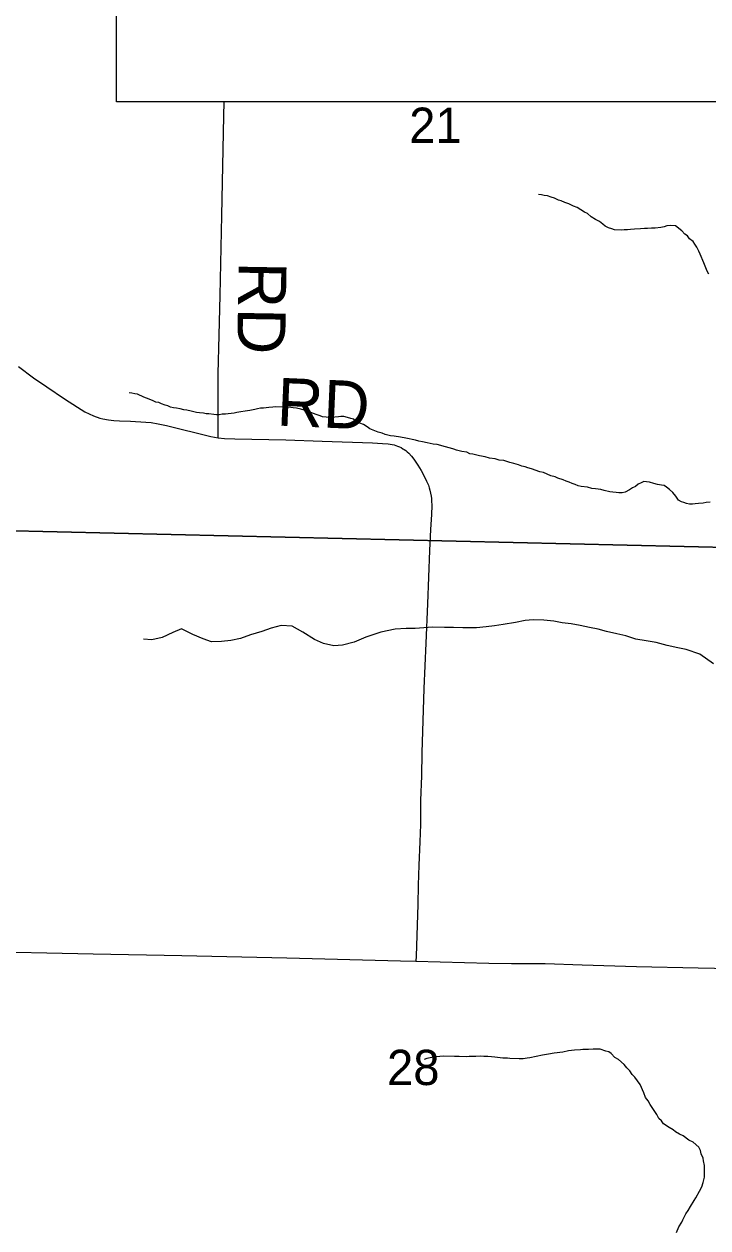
# Model space of a CAD drawing. Extents: x 0 to 34, y 0 to 22.
# Drawn here: x 25.055 to 25.461, y 15.938 to 16.653 of the extents above; entities that cross this region are included whole.
import ezdxf

# ---------------------------------------------------------------- set-up
doc = ezdxf.new("R2010")
doc.units = 0
for name, color, linetype in [('GM_X_Minor_River', 7, 'Continuous'), ('GM_X_Section', 7, 'Continuous'), ('GM_X_Section_Text', 7, 'Continuous'), ('GM_X_Township_Road', 7, 'Continuous'), ('GM_X_Township_Road_Text', 7, 'Continuous'), ('SH_Text', 7, 'Continuous')]:
    doc.layers.add(name, color=color, linetype=linetype)

msp = doc.modelspace()

# ---------------------------------------------------------------- linework, layer by layer
at = {"layer": 'GM_X_Minor_River'}
for points in [[(25.46134, 16.50449), (25.46045, 16.50623), (25.45956, 16.50816), (25.45853, 16.51124), (25.45624, 16.51627), (25.45554, 16.5182), (25.4543, 16.52053), (25.45303, 16.52228), (25.45213, 16.52384), (25.44991, 16.52544), (25.44883, 16.52719), (25.44715, 16.5282), (25.44532, 16.53017), (25.44162, 16.53315), (25.43878, 16.53344), (25.43649, 16.53314), (25.43495, 16.53262), (25.43303, 16.53212), (25.4296, 16.53186), (25.4275, 16.53174), (25.42503, 16.53163), (25.42331, 16.5315), (25.42084, 16.5314), (25.41741, 16.53114), (25.41493, 16.53104), (25.41321, 16.5309), (25.41112, 16.53079), (25.40959, 16.53065), (25.40542, 16.5308), (25.40392, 16.53142), (25.40185, 16.53206), (25.39998, 16.53308), (25.3985, 16.53408), (25.39646, 16.53568), (25.39422, 16.5369), (25.39162, 16.53851), (25.38941, 16.54049), (25.38772, 16.54131), (25.38326, 16.54413), (25.38119, 16.54477), (25.37839, 16.5462), (25.37595, 16.54705), (25.37389, 16.54807), (25.3722, 16.54851), (25.36995, 16.54954), (25.36788, 16.55018), (25.36563, 16.55102), (25.36374, 16.55128), (25.36223, 16.55152), (25.36033, 16.55178)], [(25.1971, 16.42503), (25.19539, 16.4249), (25.19367, 16.42458), (25.19213, 16.42406), (25.18907, 16.4236), (25.18639, 16.42312), (25.18372, 16.42283), (25.18142, 16.42234), (25.1797, 16.42202), (25.17626, 16.42157), (25.17473, 16.42143), (25.17264, 16.42132), (25.17091, 16.421), (25.1692, 16.42106), (25.16769, 16.42111), (25.16466, 16.4216), (25.16314, 16.42165), (25.16163, 16.42189), (25.15917, 16.42217), (25.15746, 16.42242), (25.15426, 16.4231), (25.15162, 16.42376), (25.14992, 16.42401), (25.14765, 16.42447), (25.14558, 16.42493), (25.14387, 16.42518), (25.14199, 16.42562), (25.14049, 16.42625), (25.13879, 16.42669), (25.13673, 16.42752), (25.13505, 16.42834), (25.13335, 16.42859), (25.13128, 16.42942), (25.12772, 16.43088), (25.12622, 16.4315), (25.12248, 16.43316), (25.12078, 16.43341), (25.11908, 16.43385), (25.11738, 16.4341)], [(25.43634, 16.37803), (25.43485, 16.37904), (25.43334, 16.37928), (25.43107, 16.37955), (25.42881, 16.3802), (25.42618, 16.38105), (25.42448, 16.3813), (25.42277, 16.38136), (25.42122, 16.38065), (25.41948, 16.37976), (25.41791, 16.37849), (25.41617, 16.3776), (25.41442, 16.37652), (25.41171, 16.37509), (25.40999, 16.37477), (25.40808, 16.37464), (25.40638, 16.37489), (25.40449, 16.37515), (25.40278, 16.37521), (25.39939, 16.37609), (25.39732, 16.37673), (25.3958, 16.37679), (25.3941, 16.37704), (25.39201, 16.3773), (25.38938, 16.37796), (25.38559, 16.37848), (25.3839, 16.37892), (25.38221, 16.37954), (25.38033, 16.38018), (25.37846, 16.38101), (25.37677, 16.38164), (25.3749, 16.38247), (25.37188, 16.38333), (25.3702, 16.38415), (25.36775, 16.38481), (25.36326, 16.38668), (25.36118, 16.38713), (25.35611, 16.38902), (25.35404, 16.38947), (25.35254, 16.3901), (25.35046, 16.39055), (25.34859, 16.39138), (25.34576, 16.39205), (25.34331, 16.3927), (25.33974, 16.39378), (25.33709, 16.39406), (25.33465, 16.39491), (25.33123, 16.39522), (25.32879, 16.39607), (25.32539, 16.39657), (25.32143, 16.39766), (25.31954, 16.39791), (25.31786, 16.39873), (25.31483, 16.39922), (25.31163, 16.40009), (25.31013, 16.40052), (25.30806, 16.40117), (25.30429, 16.40225), (25.30241, 16.4027), (25.30015, 16.40335), (25.29788, 16.40362), (25.29599, 16.40406), (25.29429, 16.40431), (25.29146, 16.40498), (25.28938, 16.40525), (25.28731, 16.40589), (25.28165, 16.40704), (25.27844, 16.40772), (25.27466, 16.40824), (25.27257, 16.4085), (25.26937, 16.40937), (25.26768, 16.41), (25.26523, 16.41066), (25.26036, 16.41273), (25.2587, 16.41393), (25.25646, 16.41534), (25.25439, 16.41599), (25.25197, 16.41721), (25.25049, 16.41841), (25.24898, 16.41884), (25.2471, 16.41948), (25.24484, 16.41994), (25.24313, 16.41999), (25.2416, 16.41986), (25.2395, 16.41955), (25.23683, 16.41945), (25.23437, 16.41954), (25.23228, 16.4198), (25.23079, 16.42043), (25.22834, 16.42108), (25.22534, 16.42233), (25.22289, 16.42299), (25.2214, 16.4238), (25.21932, 16.42425), (25.21668, 16.42492), (25.21479, 16.42517), (25.21195, 16.42546), (25.20416, 16.42573), (25.20264, 16.4256), (25.20035, 16.4253), (25.1971, 16.42503)], [(25.46226, 16.36913), (25.45979, 16.36903), (25.45806, 16.36852), (25.45539, 16.36842), (25.45329, 16.36811), (25.45177, 16.36798), (25.45005, 16.36785), (25.44817, 16.36829), (25.44667, 16.36892), (25.44516, 16.36935), (25.44348, 16.37036), (25.44186, 16.3727), (25.44003, 16.37486), (25.43819, 16.37664), (25.43634, 16.37803)], [(25.46412, 16.2731), (25.45614, 16.27886), (25.44807, 16.28159), (25.44299, 16.2827), (25.43677, 16.28403), (25.43019, 16.28575), (25.42415, 16.28689), (25.41811, 16.28784), (25.4121, 16.28974), (25.40683, 16.29104), (25.40062, 16.29237), (25.39573, 16.29367), (25.39064, 16.29477), (25.38517, 16.29589), (25.3797, 16.29682), (25.37442, 16.29756), (25.36951, 16.29847), (25.36346, 16.29904), (25.35721, 16.29923), (25.35246, 16.29881), (25.34673, 16.29765), (25.33949, 16.29655), (25.33416, 16.29576), (25.3294, 16.29515), (25.3235, 16.29457), (25.31554, 16.29463), (25.30985, 16.2948), (25.30454, 16.29478), (25.29753, 16.29499), (25.2924, 16.29458), (25.28708, 16.29417), (25.28177, 16.29415), (25.27531, 16.29378), (25.26672, 16.29195), (25.2579, 16.28899), (25.25098, 16.28597), (25.2441, 16.28428), (25.23897, 16.28387), (25.23275, 16.28521), (25.22752, 16.28765), (25.22045, 16.29205), (25.21411, 16.29548), (25.20767, 16.29587), (25.20175, 16.29434), (25.19619, 16.29242), (25.18949, 16.29035), (25.18354, 16.28825), (25.17782, 16.2871), (25.17229, 16.28632), (25.16623, 16.28631), (25.16135, 16.28799), (25.15517, 16.29065), (25.14844, 16.2939), (25.14345, 16.29177), (25.1371, 16.28874), (25.13099, 16.28741), (25.12607, 16.28775)], [(25.41461, 16.03156), (25.41277, 16.03334), (25.41113, 16.0353), (25.40781, 16.03827), (25.40558, 16.03949), (25.40357, 16.04184), (25.40208, 16.04284), (25.40038, 16.04328), (25.397, 16.04435), (25.39491, 16.04442), (25.39282, 16.04431), (25.38996, 16.04422), (25.38673, 16.04414), (25.3852, 16.04401), (25.38177, 16.04374), (25.37815, 16.04349), (25.37489, 16.04266), (25.36973, 16.04208), (25.36629, 16.04144), (25.36265, 16.0408), (25.35519, 16.03935), (25.35365, 16.03903), (25.35136, 16.03873), (25.34889, 16.03862), (25.34338, 16.03882), (25.34187, 16.03906), (25.33921, 16.03915), (25.33447, 16.0397), (25.33239, 16.03977), (25.3303, 16.04004), (25.32783, 16.04012), (25.32594, 16.04019), (25.32327, 16.04009), (25.31928, 16.04004), (25.31737, 16.03992), (25.31319, 16.04007), (25.31053, 16.03997), (25.30426, 16.04019), (25.30179, 16.04009), (25.29911, 16.0398), (25.29414, 16.03883), (25.2926, 16.03832)], [(25.44221, 15.93551), (25.44366, 15.93888), (25.44547, 15.94167), (25.4461, 15.94317), (25.44774, 15.94673), (25.44914, 15.94858), (25.45056, 15.951), (25.45277, 15.95454), (25.45378, 15.95621), (25.45582, 15.96013), (25.45724, 15.96275), (25.45809, 15.96519), (25.45877, 15.9684), (25.45885, 15.97049), (25.45883, 15.97543), (25.45836, 15.97811), (25.45803, 15.97964), (25.45698, 15.98234), (25.45648, 15.98426), (25.45541, 15.9862), (25.45209, 15.98917), (25.44966, 15.9904), (25.44614, 15.99299), (25.44409, 15.99401), (25.44166, 15.99524), (25.44018, 15.99643), (25.43795, 15.99784), (25.4346, 16.00005), (25.43333, 16.00181), (25.43186, 16.00319), (25.43062, 16.00571), (25.42827, 16.00921), (25.42664, 16.01155), (25.42539, 16.01369), (25.42394, 16.01564), (25.4229, 16.01853), (25.4206, 16.02336), (25.41752, 16.02785), (25.41587, 16.02943), (25.41461, 16.03156)]]:
    msp.add_lwpolyline(points, dxfattribs=at)
at = {"layer": 'GM_X_Section'}
for points in [[(25.55809, 16.8497), (25.5482, 16.34039), (25.04065, 16.35232), (25.05294, 16.85911)], [(25.04065, 16.35232), (25.5482, 16.34039), (25.53465, 15.84406), (25.03058, 15.85135)]]:
    msp.add_lwpolyline(points, close=True, dxfattribs=at)
at = {"layer": 'GM_X_Township_Road'}
for points in [[(25.17019, 16.40739), (25.17029, 16.40886), (25.17037, 16.411), (25.17026, 16.43662), (25.17036, 16.44531), (25.17089, 16.46828), (25.17148, 16.49187), (25.1724, 16.53938), (25.17374, 16.59837), (25.17393, 16.60689)], [(25.05171, 16.44972), (25.06063, 16.44298), (25.06859, 16.43756), (25.07918, 16.43048), (25.08673, 16.42555), (25.09126, 16.42285), (25.09375, 16.42157), (25.0963, 16.42044), (25.10009, 16.41904), (25.10189, 16.41858), (25.10525, 16.41798), (25.10834, 16.41764), (25.11175, 16.4175), (25.11827, 16.41724), (25.12727, 16.41671), (25.13044, 16.41642), (25.13471, 16.41568), (25.13956, 16.41462), (25.16603, 16.40804), (25.17019, 16.40739), (25.17404, 16.40702), (25.18025, 16.40681), (25.21037, 16.40613), (25.23196, 16.40541), (25.26188, 16.40436), (25.26777, 16.40404), (25.27119, 16.40378), (25.27235, 16.40363), (25.27362, 16.40337), (25.27468, 16.4031), (25.27571, 16.40276), (25.27667, 16.40244), (25.27785, 16.40198), (25.27887, 16.4015), (25.27994, 16.40087), (25.28071, 16.40036), (25.28159, 16.39976), (25.28244, 16.39901), (25.28336, 16.39816), (25.28492, 16.39651), (25.2864, 16.39466), (25.28882, 16.39113), (25.29071, 16.388), (25.29279, 16.38414), (25.294, 16.38162), (25.29509, 16.37921), (25.29558, 16.37763), (25.29596, 16.37624), (25.2963, 16.37457), (25.29659, 16.37271), (25.2968, 16.37125), (25.29687, 16.36993), (25.29697, 16.36714), (25.29684, 16.36185), (25.29637, 16.35285), (25.29574, 16.34044), (25.29445, 16.30881), (25.29348, 16.2855), (25.29242, 16.2585), (25.2912, 16.2203), (25.29092, 16.20664), (25.29043, 16.19205), (25.29028, 16.17771), (25.28992, 16.16747), (25.28927, 16.15354), (25.28904, 16.14173), (25.28871, 16.13025), (25.28771, 16.09955), (25.28765, 16.09663)], [(25.02258, 16.10251), (25.09619, 16.10096), (25.14867, 16.09994), (25.21109, 16.09865), (25.27847, 16.09688), (25.28765, 16.09663), (25.33096, 16.09542), (25.34432, 16.09535), (25.36004, 16.09536), (25.3644, 16.09527), (25.38623, 16.09445), (25.41851, 16.09353), (25.45515, 16.09272), (25.51323, 16.09152)]]:
    msp.add_lwpolyline(points, dxfattribs=at)
at = {"layer": 'SH_Text'}
msp.add_lwpolyline([(25.10999, 17.00998), (27.04336, 17.00998), (27.04336, 16.60689), (25.10999, 16.60689), (25.10999, 16.70766), (24.55424, 17.11998), (25.10999, 16.80843)], close=True, dxfattribs=at)

# ---------------------------------------------------------------- texts
at = {"layer": 'GM_X_Section_Text'}
for s, p in [('21', (25.28363, 16.58243)), ('28', (25.2705, 16.02311))]:
    msp.add_text(s, height=0.020928, rotation=0.00001, dxfattribs=at).set_placement(p)
at = {"layer": 'GM_X_Township_Road_Text'}
for rotation, p in [(269.01181, (25.1825, 16.51205)), (357.53136, (25.20473, 16.41465))]:
    msp.add_text('RD', height=0.028409, rotation=rotation, dxfattribs=at).set_placement(p)

doc.saveas('drawing.dxf')
